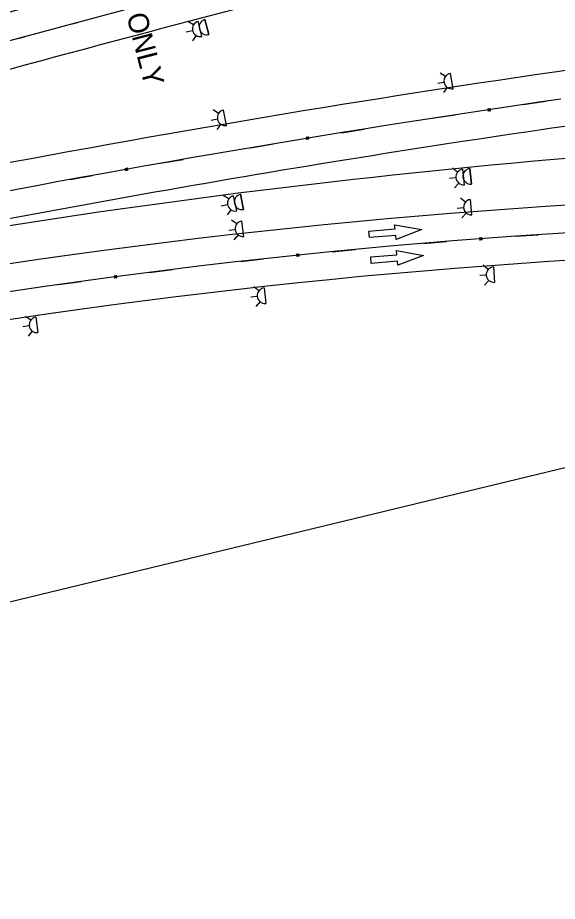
# Model space of a CAD drawing. Extents: x 2471014 to 2497726, y 6959577 to 6980268.
# Drawn here: x 2486692 to 2486927, y 6968041.1 to 6968425.6 of the extents above; entities that cross this region are included whole.
import ezdxf

# ---------------------------------------------------------------- set-up
doc = ezdxf.new("R2010")
doc.units = 0
for name, color, linetype in [('1', 7, 'Continuous'), ('13', 7, 'Continuous'), ('18', 7, 'Continuous'), ('23', 7, 'Continuous'), ('5', 7, 'Continuous'), ('59', 7, 'Continuous'), ('ALIGN_ML_IH35_NB_SB', 7, 'Continuous'), ('C-ANNO-NOTE', 7, 'Continuous'), ('C-COMM-IDEN', 7, 'Continuous'), ('Level 30', 7, 'Continuous'), ('Level 40', 7, 'Continuous'), ('p_structure fence', 7, 'Continuous'), ('PMK_Del_D-SY_SZ_TYC_CTB', 7, 'Continuous'), ('S-BRDG-DECK', 7, 'Continuous'), ('V7_25', 7, 'Continuous'), ('V7_50', 7, 'Continuous')]:
    doc.layers.add(name, color=color, linetype=linetype)

msp = doc.modelspace()

# ---------------------------------------------------------------- linework, layer by layer
at = {"layer": '1'}
for p, q in [((2486912.08, 6968387.76), (2486921.97, 6968389.21)), ((2486872.52, 6968381.78), (2486882.41, 6968383.3)), ((2486833.02, 6968375.53), (2486842.89, 6968377.12)), ((2486793.55, 6968369.01), (2486803.41, 6968370.67)), ((2486754.13, 6968362.21), (2486763.98, 6968363.93)), ((2486714.76, 6968355.13), (2486724.6, 6968356.93)), ((2486908.62, 6968330.47), (2486918.6, 6968331.15)), ((2486868.74, 6968327.39), (2486878.71, 6968328.22)), ((2486828.91, 6968323.75), (2486838.86, 6968324.71)), ((2486789.13, 6968319.54), (2486799.07, 6968320.65)), ((2486749.42, 6968314.77), (2486759.34, 6968316.01)), ((2486709.78, 6968309.43), (2486719.68, 6968310.81))]:
    msp.add_line(p, q, dxfattribs=at)
at = {"layer": '13'}
for centre, radius, start, end in [((2488909.95, 6960235.84), 8500, 104.374936, 107.663843), ((2487394.89, 6965163.69), 3272, 94.97447, 98.22581), ((2487750.43, 6962704.26), 5757, 98.225813, 103.699749), ((2487104.97, 6965525.33), 2824, 86.42652, 104.37494)]:
    msp.add_arc(centre, radius, start, end, dxfattribs=at)
at = {"layer": '18'}
for centre, radius, start, end in [((2488909.95, 6960235.84), 8464, 104.374936, 107.367847), ((2487228.35, 6964876.97), 3500, 91.74605, 100.77259), ((2487104.97, 6965525.33), 2800, 86.42652, 104.37494)]:
    msp.add_arc(centre, radius, start, end, dxfattribs=at)
at = {"layer": '23'}
for p, q in [((2486896.66, 6968385.97), (2486897.67, 6968386.12)), ((2486896.85, 6968385.83), (2486896.66, 6968385.97)), ((2486896.66, 6968385.97), (2486896.7, 6968385.7)), ((2486896.7, 6968385.7), (2486896.81, 6968384.96)), ((2486896.81, 6968384.96), (2486896.95, 6968385.16)), ((2486897.82, 6968385.11), (2486896.81, 6968384.96)), ((2486896.95, 6968385.16), (2486896.85, 6968385.83)), ((2486897.67, 6968386.12), (2486897.52, 6968385.93)), ((2486897.52, 6968385.93), (2486897.54, 6968385.79)), ((2486897.54, 6968385.79), (2486897.62, 6968385.26)), ((2486897.62, 6968385.26), (2486897.82, 6968385.11)), ((2486897.82, 6968385.11), (2486897.67, 6968386.12)), ((2486817.63, 6968373.53), (2486818.63, 6968373.69)), ((2486817.82, 6968373.4), (2486817.63, 6968373.53)), ((2486817.63, 6968373.53), (2486817.67, 6968373.26)), ((2486817.67, 6968373.26), (2486817.79, 6968372.53)), ((2486817.79, 6968372.53), (2486817.93, 6968372.73)), ((2486818.8, 6968372.69), (2486817.79, 6968372.53)), ((2486817.93, 6968372.73), (2486817.82, 6968373.4)), ((2486818.63, 6968373.69), (2486818.49, 6968373.51)), ((2486818.49, 6968373.51), (2486818.51, 6968373.37)), ((2486818.51, 6968373.37), (2486818.6, 6968372.84)), ((2486818.6, 6968372.84), (2486818.8, 6968372.69)), ((2486818.8, 6968372.69), (2486818.63, 6968373.69)), ((2486738.78, 6968359.99), (2486739.78, 6968360.17)), ((2486738.97, 6968359.86), (2486738.78, 6968359.99)), ((2486738.78, 6968359.99), (2486738.82, 6968359.72)), ((2486738.82, 6968359.72), (2486738.96, 6968358.99)), ((2486738.96, 6968358.99), (2486739.09, 6968359.19)), ((2486739.95, 6968359.17), (2486738.96, 6968358.99)), ((2486739.09, 6968359.19), (2486738.97, 6968359.86)), ((2486739.78, 6968360.17), (2486739.64, 6968359.98)), ((2486739.64, 6968359.98), (2486739.66, 6968359.84)), ((2486739.66, 6968359.84), (2486739.76, 6968359.31)), ((2486739.76, 6968359.31), (2486739.95, 6968359.17)), ((2486739.95, 6968359.17), (2486739.78, 6968360.17)), ((2486893.12, 6968329.84), (2486894.13, 6968329.92)), ((2486893.3, 6968329.7), (2486893.12, 6968329.84)), ((2486893.12, 6968329.84), (2486893.14, 6968329.57)), ((2486893.14, 6968329.57), (2486893.2, 6968328.83)), ((2486893.2, 6968328.83), (2486893.35, 6968329.02)), ((2486894.21, 6968328.91), (2486893.2, 6968328.83)), ((2486893.35, 6968329.02), (2486893.3, 6968329.7)), ((2486894.13, 6968329.92), (2486893.97, 6968329.75)), ((2486893.97, 6968329.75), (2486893.98, 6968329.6)), ((2486893.98, 6968329.6), (2486894.03, 6968329.07)), ((2486894.03, 6968329.07), (2486894.21, 6968328.91)), ((2486894.21, 6968328.91), (2486894.13, 6968329.92)), ((2486813.43, 6968322.68), (2486814.44, 6968322.79)), ((2486813.61, 6968322.54), (2486813.43, 6968322.68)), ((2486813.43, 6968322.68), (2486813.46, 6968322.41)), ((2486814.44, 6968322.79), (2486814.29, 6968322.61)), ((2486814.54, 6968321.78), (2486814.44, 6968322.79)), ((2486813.46, 6968322.41), (2486813.53, 6968321.67)), ((2486813.53, 6968321.67), (2486813.68, 6968321.87)), ((2486814.54, 6968321.78), (2486813.53, 6968321.67)), ((2486813.68, 6968321.87), (2486813.61, 6968322.54)), ((2486814.29, 6968322.61), (2486814.3, 6968322.47)), ((2486814.3, 6968322.47), (2486814.36, 6968321.94)), ((2486814.36, 6968321.94), (2486814.54, 6968321.78)), ((2486733.97, 6968313.26), (2486734.98, 6968313.39)), ((2486734.16, 6968313.12), (2486733.97, 6968313.26)), ((2486733.97, 6968313.26), (2486734.01, 6968312.99)), ((2486734.01, 6968312.99), (2486734.11, 6968312.25)), ((2486734.11, 6968312.25), (2486734.25, 6968312.45)), ((2486735.11, 6968312.38), (2486734.11, 6968312.25)), ((2486734.25, 6968312.45), (2486734.16, 6968313.12)), ((2486734.98, 6968313.39), (2486734.83, 6968313.21)), ((2486734.83, 6968313.21), (2486734.85, 6968313.07)), ((2486734.85, 6968313.07), (2486734.92, 6968312.54)), ((2486734.92, 6968312.54), (2486735.11, 6968312.38)), ((2486735.11, 6968312.38), (2486734.98, 6968313.39))]:
    msp.add_line(p, q, dxfattribs=at)
for points in [[(2486896.85, 6968385.83), (2486897.52, 6968385.93), (2486897.62, 6968385.26), (2486896.95, 6968385.16)], [(2486817.82, 6968373.4), (2486818.49, 6968373.51), (2486818.6, 6968372.84), (2486817.93, 6968372.73)], [(2486738.97, 6968359.86), (2486739.64, 6968359.98), (2486739.76, 6968359.31), (2486739.09, 6968359.19)], [(2486893.3, 6968329.7), (2486893.97, 6968329.75), (2486894.03, 6968329.07), (2486893.35, 6968329.02)], [(2486813.61, 6968322.54), (2486814.29, 6968322.61), (2486814.36, 6968321.94), (2486813.68, 6968321.87)], [(2486734.16, 6968313.12), (2486734.83, 6968313.21), (2486734.92, 6968312.54), (2486734.25, 6968312.45)]]:
    msp.add_lwpolyline(points, close=True, dxfattribs=at)
at = {"layer": '5'}
msp.add_arc((2479474.04, 6969335.88), 8460, 6.37617, 6.37617, dxfattribs=at)
at = {"layer": '59'}
msp.add_arc((2488909.95, 6960235.84), 8476, 104.517558, 107.663843, dxfattribs=at)
at = {"layer": 'ALIGN_ML_IH35_NB_SB'}
for p, q in [((2486856.27, 6968333.68), (2486856.11, 6968335.47)), ((2486856.11, 6968335.47), (2486867.92, 6968333.37)), ((2486844.94, 6968332.68), (2486856.27, 6968333.68)), ((2486845.19, 6968329.87), (2486844.94, 6968332.68)), ((2486856.58, 6968330.87), (2486845.19, 6968329.87)), ((2486856.73, 6968329.08), (2486856.58, 6968330.87)), ((2486867.92, 6968333.37), (2486856.73, 6968329.08)), ((2486857.03, 6968322.44), (2486856.88, 6968324.23)), ((2486856.88, 6968324.23), (2486868.68, 6968322.13)), ((2486845.71, 6968321.45), (2486857.03, 6968322.44)), ((2486845.95, 6968318.64), (2486845.71, 6968321.45)), ((2486857.34, 6968319.63), (2486845.95, 6968318.64)), ((2486857.5, 6968317.84), (2486857.34, 6968319.63)), ((2486868.68, 6968322.13), (2486857.5, 6968317.84))]:
    msp.add_line(p, q, dxfattribs=at)
at = {"layer": 'C-ANNO-NOTE'}
for centre, radius, start, end in [((2487750.43, 6962704.26), 5745, 98.225813, 104.374936), ((2487104.97, 6965525.33), 2812, 86.42652, 104.37494)]:
    msp.add_arc(centre, radius, start, end, dxfattribs=at)
at = {"layer": 'C-COMM-IDEN'}
for p, q in [((2486768.5, 6968422.44), (2486766.07, 6968423.85)), ((2486772.23, 6968417.44), (2486770.57, 6968423.99)), ((2486773.53, 6968424.74), (2486775.19, 6968418.19)), ((2486775.19, 6968418.19), (2486773.53, 6968424.74)), ((2486768.13, 6968419.89), (2486765.4, 6968419.2)), ((2486769.67, 6968417.82), (2486768.14, 6968415.46)), ((2486883.54, 6968358.38), (2486881.34, 6968360.13)), ((2486886.48, 6968352.89), (2486885.81, 6968359.6)), ((2486888.85, 6968359.91), (2486889.52, 6968353.19)), ((2486889.52, 6968353.19), (2486888.85, 6968359.91)), ((2486882.79, 6968355.91), (2486879.99, 6968355.63)), ((2486884.01, 6968353.63), (2486882.15, 6968351.53)), ((2486783.87, 6968346.69), (2486781.51, 6968348.22)), ((2486787.34, 6968341.51), (2486786.02, 6968348.13)), ((2486789.01, 6968348.73), (2486790.34, 6968342.11)), ((2486790.34, 6968342.11), (2486789.01, 6968348.73)), ((2486783.37, 6968344.16), (2486780.61, 6968343.61)), ((2486784.81, 6968342.01), (2486783.16, 6968339.73))]:
    msp.add_line(p, q, dxfattribs=at)
for centre, start, end in [((2486771.4, 6968420.71), 104.1995, 284.1995), ((2486774.36, 6968421.46), 104.1995, 284.1995), ((2486886.15, 6968356.25), 95.7004, 275.7004), ((2486889.19, 6968356.55), 95.7004, 275.7004), ((2486786.68, 6968344.82), 101.3322, 281.3322), ((2486789.68, 6968345.42), 101.3322, 281.3322)]:
    msp.add_arc(centre, 3.37, start, end, dxfattribs=at)
at = {"layer": 'Level 30'}
for p, q in [((2486896.84, 6968316), (2486894.7, 6968317.83)), ((2486899.16, 6968317.14), (2486899.58, 6968310.41)), ((2486896, 6968313.56), (2486893.2, 6968313.38)), ((2486897.14, 6968311.24), (2486895.2, 6968309.2)), ((2486797.04, 6968306.76), (2486794.84, 6968308.51)), ((2486799.32, 6968307.98), (2486799.98, 6968301.26)), ((2486796.29, 6968304.29), (2486793.49, 6968304.01)), ((2486797.51, 6968302.01), (2486795.65, 6968299.91)), ((2486697.64, 6968293.95), (2486695.38, 6968295.62)), ((2486699.87, 6968295.25), (2486700.78, 6968288.56)), ((2486696.98, 6968291.45), (2486694.19, 6968291.07)), ((2486698.28, 6968289.22), (2486696.49, 6968287.05))]:
    msp.add_line(p, q, dxfattribs=at)
for centre, start, end in [((2486899.37, 6968313.77), 93.6223, 273.6223), ((2486799.65, 6968304.62), 95.6745, 275.6744), ((2486700.32, 6968291.91), 97.7266, 277.7266)]:
    msp.add_arc(centre, 3.37, start, end, dxfattribs=at)
at = {"layer": 'Level 40'}
for p, q in [((2486715.17, 6968422.76), (2486718.07, 6968423.53)), ((2486703.59, 6968419.64), (2486706.48, 6968420.42)), ((2486692, 6968416.51), (2486694.9, 6968417.29))]:
    msp.add_line(p, q, dxfattribs=at)
at = {"layer": 'PMK_Del_D-SY_SZ_TYC_CTB'}
for p, q in [((2486878.21, 6968399.91), (2486875.88, 6968401.49)), ((2486881.56, 6968394.66), (2486880.38, 6968401.3)), ((2486877.65, 6968397.39), (2486874.88, 6968396.9)), ((2486879.04, 6968395.21), (2486877.34, 6968392.97)), ((2486779.48, 6968383.91), (2486777.12, 6968385.45)), ((2486782.92, 6968378.72), (2486781.63, 6968385.34)), ((2486778.96, 6968381.38), (2486776.2, 6968380.84)), ((2486780.39, 6968379.23), (2486778.73, 6968376.96)), ((2486886.91, 6968345.29), (2486884.73, 6968347.08)), ((2486889.78, 6968339.76), (2486889.2, 6968346.48)), ((2486886.13, 6968342.83), (2486883.33, 6968342.59)), ((2486887.32, 6968340.54), (2486885.43, 6968338.46)), ((2486787.35, 6968335.82), (2486785.11, 6968337.53)), ((2486790.42, 6968330.39), (2486789.6, 6968337.09)), ((2486786.66, 6968333.33), (2486783.87, 6968332.99)), ((2486787.93, 6968331.08), (2486786.11, 6968328.94))]:
    msp.add_line(p, q, dxfattribs=at)
for centre, start, end in [((2486880.97, 6968397.98), 100.0728, 280.0728), ((2486782.28, 6968382.03), 101.0674, 281.0674), ((2486889.49, 6968343.12), 94.9155, 274.9155), ((2486790.01, 6968333.74), 96.9415, 276.9415)]:
    msp.add_arc(centre, 3.37, start, end, dxfattribs=at)
at = {"layer": 'S-BRDG-DECK'}
msp.add_arc((2487750.43, 6962704.26), 5733, 98.225813, 101.840567, dxfattribs=at)
at = {"layer": 'V7_25'}
msp.add_arc((2488909.95, 6960235.84), 8488, 104.374936, 107.663843, dxfattribs=at)
at = {"layer": 'V7_50'}
msp.add_lwpolyline([(2484447.6, 6967710.17), (2484746.88, 6967763.8), (2484810.56, 6967778.56), (2485254.64, 6967806.33), (2486523.86, 6968131.62), (2487206.36, 6968296.54)], dxfattribs=at)

# ---------------------------------------------------------------- texts
at = {"layer": 'p_structure fence'}
msp.add_text('ONLY', height=8.898, rotation=284.3716, dxfattribs=at).set_placement((2486739.29, 6968426.56))

doc.saveas('drawing.dxf')
